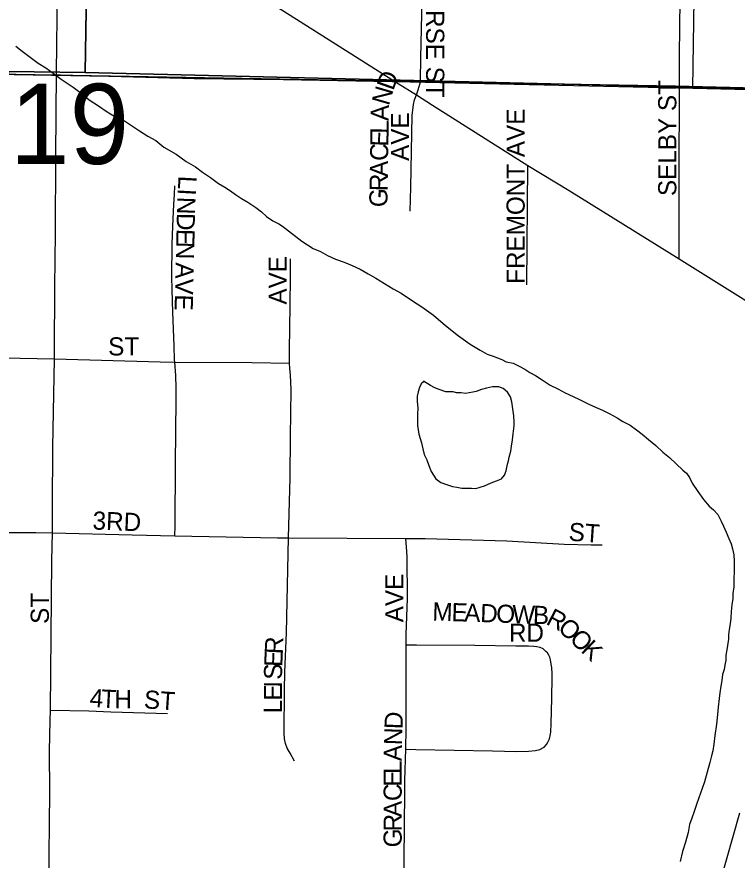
# Model space of a CAD drawing. Extents: x 0 to 68, y 0 to 52.9.
# Drawn here: x 44.4147 to 44.8116, y 37.5049 to 37.9697 of the extents above; entities that cross this region are included whole.
import ezdxf

# ---------------------------------------------------------------- set-up
doc = ezdxf.new("R2010")
doc.units = 0
for name, color, linetype in [('Default', 7, 'Continuous'), ('GM_X_Minor_Lake', 7, 'Continuous'), ('GM_X_Minor_River', 7, 'Continuous'), ('GM_X_State_Route', 7, 'Continuous'), ('GM_X_Township', 7, 'Continuous'), ('GM_X_Township_Road', 7, 'Continuous')]:
    doc.layers.add(name, color=color, linetype=linetype)

msp = doc.modelspace()

# ---------------------------------------------------------------- linework, layer by layer
at = {"layer": 'Default'}
for points in [[(43.1609, 39.26536), (44.47349, 39.25009), (44.45233, 37.93902), (44.41032, 37.93957), (43.13273, 37.95279)], [(45.79985, 39.21605), (45.7821, 37.90702), (45.7586, 37.9073), (44.45233, 37.93902), (44.47349, 39.25009)], [(44.41032, 37.93957), (44.45233, 37.93902), (45.7586, 37.9073), (45.68961, 36.62483), (44.34414, 36.66665)]]:
    msp.add_lwpolyline(points, close=True, dxfattribs=at)
for points in [[(44.63484, 37.92679), (44.63585, 37.92946), (44.63699, 37.93323), (44.63703, 37.93498), (44.63731, 37.94701), (44.63811, 37.97967), (44.63852, 37.99959), (44.63871, 38.02121), (44.63881, 38.07442), (44.63854, 38.0814)], [(44.43533, 37.78123), (44.43536, 37.78496), (44.43555, 37.82108), (44.43597, 37.85053), (44.43607, 37.89319), (44.43648, 37.93913), (44.43704, 37.9848), (44.4374, 38.00679), (44.43731, 38.02977), (44.43752, 38.05165)], [(44.77962, 37.83631), (44.77965, 37.84375), (44.77967, 37.84635), (44.77965, 37.87219), (44.77965, 37.88197), (44.77985, 37.93041), (44.77993, 37.94854), (44.78032, 37.97938), (44.78019, 37.98435), (44.78014, 37.99056)], [(44.63141, 37.86268), (44.63174, 37.87595), (44.63253, 37.9154), (44.63319, 37.92146), (44.63378, 37.924), (44.63484, 37.92679)], [(44.69572, 37.82197), (44.69622, 37.88784)], [(44.50166, 37.7794), (44.50157, 37.78074), (44.50129, 37.78834), (44.50061, 37.80689), (44.50017, 37.81925), (44.50005, 37.82665), (44.50028, 37.8444), (44.50061, 37.85432), (44.50125, 37.86631), (44.50156, 37.8718), (44.50177, 37.87669)], [(44.56492, 37.77879), (44.56494, 37.786), (44.56529, 37.81058), (44.56556, 37.82637), (44.56548, 37.83171), (44.56538, 37.83645)], [(44.28088, 37.78471), (44.30189, 37.78421), (44.34421, 37.7832), (44.38776, 37.78219), (44.43533, 37.78123)], [(44.43422, 37.68534), (44.43437, 37.69969), (44.43456, 37.73249), (44.43533, 37.78123)], [(44.43533, 37.78123), (44.49355, 37.77964), (44.50166, 37.7794)], [(44.50163, 37.68374), (44.50182, 37.68912), (44.50211, 37.72346), (44.50246, 37.75866), (44.5024, 37.76532), (44.50221, 37.77205), (44.50166, 37.7794)], [(44.50166, 37.7794), (44.5442, 37.77925), (44.56492, 37.77879)], [(44.56431, 37.6826), (44.56532, 37.71582), (44.56543, 37.73845), (44.56575, 37.76413), (44.56538, 37.77245), (44.56513, 37.77594), (44.56492, 37.77879)], [(44.38451, 37.68566), (44.39399, 37.68548), (44.4251, 37.68558), (44.43422, 37.68534)], [(44.43311, 37.58761), (44.43401, 37.67016), (44.43422, 37.68534)], [(44.43422, 37.68534), (44.47813, 37.68415), (44.50163, 37.68374)], [(44.50163, 37.68374), (44.55832, 37.68266), (44.56431, 37.6826)], [(44.56769, 37.55952), (44.56525, 37.56381), (44.56366, 37.56669), (44.56275, 37.56915), (44.56221, 37.57172), (44.56193, 37.57499), (44.56218, 37.5987), (44.56239, 37.60856), (44.5633, 37.63021), (44.56431, 37.6826)], [(44.56431, 37.6826), (44.62906, 37.68226)], [(44.62906, 37.68226), (44.63965, 37.68228), (44.68469, 37.68085), (44.71637, 37.67916), (44.73118, 37.6787), (44.73723, 37.67871)], [(44.62927, 37.62366), (44.62929, 37.62932), (44.62989, 37.64908), (44.62976, 37.67187), (44.62954, 37.6751), (44.62906, 37.68226)], [(44.62898, 37.56606), (44.62917, 37.57739), (44.62917, 37.58394), (44.62919, 37.59986), (44.62927, 37.62366)], [(44.62927, 37.62366), (44.63494, 37.62361), (44.66708, 37.62335), (44.68969, 37.62303), (44.69656, 37.62302), (44.69967, 37.62281), (44.70128, 37.62265), (44.70293, 37.62226), (44.70451, 37.6215), (44.70616, 37.61999)], [(44.70529, 37.56721), (44.7065, 37.56866), (44.70732, 37.56994), (44.70815, 37.57184), (44.70878, 37.57437), (44.70893, 37.57558), (44.70922, 37.58007), (44.70948, 37.59427), (44.70963, 37.60579), (44.70961, 37.60763), (44.70941, 37.6111), (44.70918, 37.61302), (44.70876, 37.6153), (44.70838, 37.61675), (44.70787, 37.61789), (44.70704, 37.6191), (44.70616, 37.61999)], [(44.43227, 37.4907), (44.43277, 37.54226), (44.43273, 37.56524), (44.43292, 37.58162), (44.43311, 37.58761)], [(44.43311, 37.58761), (44.45439, 37.58713), (44.46649, 37.58674), (44.49765, 37.58571)], [(44.62788, 37.48889), (44.62836, 37.52296), (44.62854, 37.54361), (44.62857, 37.54875), (44.62898, 37.56606)], [(44.62898, 37.56606), (44.6345, 37.56595), (44.67687, 37.56517), (44.6901, 37.56488), (44.69671, 37.56506), (44.70044, 37.56534), (44.70295, 37.56594), (44.70529, 37.56721)], [(44.7737, 37.38631), (44.77418, 37.38918), (44.77571, 37.39488), (44.79524, 37.46651), (44.8022, 37.49277), (44.81318, 37.53091)]]:
    msp.add_lwpolyline(points, dxfattribs=at)
at = {"layer": 'GM_X_Minor_Lake'}
for points in [[(44.64267, 37.76648), (44.63871, 37.76897), (44.6387, 37.76856), (44.63747, 37.76739), (44.63663, 37.7654), (44.63578, 37.76301), (44.63533, 37.76061), (44.63527, 37.7578), (44.6356, 37.75418), (44.63553, 37.75057), (44.6354, 37.74456), (44.63576, 37.74214), (44.63611, 37.73973), (44.63686, 37.73731), (44.63762, 37.73488), (44.63835, 37.73166), (44.63909, 37.72844), (44.64064, 37.7256), (44.64178, 37.72236), (44.64292, 37.71913), (44.64564, 37.71506), (44.64841, 37.713), (44.652, 37.71173), (44.65479, 37.71087), (44.65719, 37.71042), (44.65999, 37.70996), (44.6632, 37.70989), (44.6652, 37.70986), (44.66761, 37.70981), (44.67003, 37.71056), (44.67246, 37.71131), (44.6761, 37.71284), (44.67893, 37.71399), (44.68176, 37.71514), (44.68341, 37.71711), (44.68426, 37.7195), (44.68514, 37.72309), (44.68558, 37.72509), (44.68602, 37.72709), (44.68689, 37.73028), (44.68734, 37.73308), (44.68782, 37.73668), (44.68828, 37.73988), (44.68877, 37.74429), (44.68882, 37.74629), (44.68849, 37.74991), (44.68744, 37.75755), (44.68669, 37.76038), (44.68514, 37.76281), (44.68277, 37.76487), (44.68038, 37.76572), (44.67677, 37.76579), (44.67354, 37.76505), (44.67072, 37.76431), (44.66789, 37.76316), (44.66587, 37.7628), (44.66386, 37.76244), (44.66185, 37.76208), (44.65945, 37.76253), (44.65704, 37.76258), (44.65504, 37.76302), (44.65304, 37.76306), (44.65103, 37.7631)], [(44.65103, 37.7631), (44.64745, 37.76438), (44.64505, 37.76523), (44.64267, 37.76648)]]:
    msp.add_lwpolyline(points, dxfattribs=at)
at = {"layer": 'GM_X_Minor_River'}
for points in [[(44.4141, 37.95364), (44.41765, 37.95076), (44.422, 37.94746), (44.42635, 37.94416), (44.43071, 37.94167), (44.43466, 37.93878), (44.43901, 37.93548), (44.44574, 37.93093), (44.45009, 37.92763), (44.45443, 37.92394), (44.45958, 37.92062), (44.46393, 37.91773)], [(44.46393, 37.91773), (44.46869, 37.91482), (44.47347, 37.91272), (44.47782, 37.90982), (44.48218, 37.90693), (44.48693, 37.90402), (44.4913, 37.90153), (44.49564, 37.89783), (44.50239, 37.89408), (44.50792, 37.88996), (44.51308, 37.88705), (44.51703, 37.88416), (44.52139, 37.88126), (44.52574, 37.87797), (44.52931, 37.87589), (44.53248, 37.87382), (44.53524, 37.87176), (44.53841, 37.86969), (44.54198, 37.86761), (44.54634, 37.86471), (44.5495, 37.86224), (44.55226, 37.85978), (44.55582, 37.8573), (44.559, 37.85563), (44.56098, 37.85439), (44.57165, 37.84615), (44.57481, 37.84408), (44.57798, 37.84201), (44.58196, 37.84032), (44.58593, 37.83823), (44.59031, 37.83614), (44.59509, 37.83444), (44.59947, 37.83275), (44.60384, 37.83065), (44.6082, 37.82816), (44.61257, 37.82566), (44.61733, 37.82276), (44.62208, 37.81985), (44.62645, 37.81736), (44.63278, 37.81322), (44.63793, 37.8099), (44.64426, 37.80536), (44.65097, 37.79961), (44.65807, 37.79385), (44.66441, 37.78931), (44.66996, 37.78599), (44.67393, 37.7839), (44.67711, 37.78264), (44.6795, 37.78179), (44.68189, 37.78093), (44.68428, 37.77968), (44.68827, 37.7788), (44.69145, 37.77713), (44.69463, 37.77546), (44.6974, 37.7738), (44.70058, 37.77213), (44.70414, 37.76965), (44.7085, 37.76676), (44.71287, 37.76466), (44.71684, 37.76258), (44.72121, 37.76048), (44.72479, 37.75881), (44.72995, 37.75629), (44.73353, 37.75462), (44.73751, 37.75293), (44.74148, 37.75085), (44.74545, 37.74876), (44.74862, 37.74669), (44.75259, 37.7446), (44.75616, 37.74212), (44.75932, 37.73966), (44.76287, 37.73677), (44.76682, 37.73349), (44.77075, 37.72979), (44.77431, 37.72691), (44.78179, 37.71994), (44.78377, 37.7183), (44.78532, 37.71586), (44.78686, 37.71262), (44.78998, 37.70814), (44.7931, 37.70367), (44.79624, 37.69999), (44.7986, 37.69794), (44.80096, 37.69549), (44.80289, 37.69183), (44.80404, 37.689), (44.80558, 37.68576), (44.80711, 37.68212), (44.80826, 37.67929), (44.809, 37.67647), (44.80974, 37.67324), (44.81007, 37.66962), (44.80996, 37.66441), (44.80987, 37.6596), (44.80978, 37.65559), (44.80931, 37.65198), (44.80925, 37.64918), (44.80878, 37.64558), (44.8083, 37.64198), (44.80823, 37.63837), (44.80777, 37.63516)], [(44.80777, 37.63516), (44.8073, 37.63196), (44.80684, 37.62917), (44.80679, 37.62676), (44.80632, 37.62316), (44.80587, 37.62076), (44.80541, 37.61796), (44.80535, 37.61515), (44.80489, 37.61235), (44.80444, 37.60996), (44.80359, 37.60716), (44.80312, 37.60396), (44.80265, 37.60076), (44.80218, 37.59716), (44.80171, 37.59396), (44.80121, 37.58916), (44.80073, 37.58516), (44.80022, 37.57995), (44.79929, 37.57355), (44.79879, 37.56875), (44.79832, 37.56514), (44.79746, 37.56235), (44.79658, 37.55876), (44.79356, 37.54799), (44.79228, 37.5444), (44.79057, 37.53922), (44.78929, 37.53564), (44.78801, 37.53165), (44.78673, 37.52806), (44.78545, 37.52448), (44.78456, 37.52008), (44.78325, 37.51489), (44.78154, 37.50971), (44.78023, 37.50412)]]:
    msp.add_lwpolyline(points, dxfattribs=at)
at = {"layer": 'GM_X_State_Route'}
msp.add_lwpolyline([(44.54231, 37.98537), (44.58338, 37.95928), (44.62473, 37.93299), (44.63484, 37.92679), (44.64377, 37.92108), (44.69622, 37.88784), (44.71909, 37.87397), (44.77962, 37.83631), (44.81636, 37.81343), (44.83491, 37.80242), (44.86599, 37.78206), (44.88016, 37.77305), (44.9046, 37.75749), (44.95765, 37.72432), (44.9925, 37.70213), (45.02038, 37.68482), (45.05414, 37.66367), (45.06975, 37.6539), (45.09194, 37.63991), (45.14814, 37.60465), (45.20303, 37.57021), (45.21358, 37.56348)], dxfattribs=at)
at = {"layer": 'GM_X_Township'}
for points in [[(50.34506, 37.77433), (49.87003, 37.78728), (49.7424, 37.78907), (49.09193, 37.81286), (48.42924, 37.83782), (47.97584, 37.8521), (47.09341, 37.87493), (46.43542, 37.88698), (45.78152, 37.90751), (45.76356, 37.9078), (44.77759, 37.93161), (44.12143, 37.94309), (43.3203, 37.94792), (43.31455, 37.9477), (43.13228, 37.95106), (43.13722, 38.12535), (43.1394, 38.18651), (43.13947, 38.19396), (43.15039, 38.61621), (43.15805, 38.89613)], [(43.06441, 32.7683), (43.08393, 33.99592), (43.08445, 34.02868), (43.09249, 34.65268), (43.09292, 34.68642), (43.10458, 35.31419), (43.1053, 35.34562), (43.1113, 36.01383), (43.1191, 36.64269), (43.12347, 37.01757), (43.12518, 37.25841), (43.12908, 37.42523), (43.12464, 37.49311), (43.12504, 37.51468), (43.13199, 37.8314), (43.13205, 37.85841), (43.13228, 37.95106), (43.31455, 37.9477), (43.3203, 37.94792), (44.12143, 37.94309), (44.77759, 37.93161), (45.76356, 37.9078)]]:
    msp.add_lwpolyline(points, dxfattribs=at)
at = {"layer": 'GM_X_Township_Road'}
for points in [[(44.7872, 37.93047), (44.78916, 38.0655), (44.79016, 38.11876), (44.79071, 38.17209), (44.79244, 38.2459), (44.79316, 38.30333), (44.79602, 38.45915), (44.79696, 38.52068), (44.79793, 38.56987), (44.79919, 38.6847), (44.79993, 38.77083), (44.80072, 38.85276), (44.80196, 38.93851), (44.80314, 39.05312), (44.80377, 39.09415), (44.80406, 39.13866), (44.8054, 39.1908), (44.80605, 39.24618)], [(44.13006, 37.94547), (44.13366, 37.9422), (44.13919, 37.94017), (44.1456, 37.93958), (44.15418, 37.93958), (44.17426, 37.93982), (44.21509, 37.93939), (44.30327, 37.93917), (44.43863, 37.93782), (44.51244, 37.93583), (44.56165, 37.93528), (44.63137, 37.93387), (44.7872, 37.93047)], [(44.7872, 37.93047), (44.85691, 37.92882), (44.93892, 37.9272), (45.11526, 37.9236), (45.28748, 37.91961), (45.33668, 37.91828), (45.4638, 37.91529), (45.57041, 37.9127), (45.66883, 37.91037), (45.75084, 37.90855), (45.76151, 37.90822)]]:
    msp.add_lwpolyline(points, dxfattribs=at)

# ---------------------------------------------------------------- texts
at = {"layer": 'Default'}
for s, height, rotation, p in [('MORSE ST', 0.01, 270, (44.64022, 37.99506)), ('D', 0.01, 70.549, (44.62208, 37.9287)), ('19', 0.0442, 0, (44.41085, 37.88865)), ('N', 0.01, 73.6733, (44.61965, 37.92039)), ('SELBY ST', 0.01, 90, (44.77813, 37.87098)), ('A', 0.01, 89.0819, (44.61962, 37.91229)), ('AVE', 0.01, 90, (44.63078, 37.89034)), ('FREMONT AVE', 0.01, 90, (44.69453, 37.82258)), ('L', 0.01, 89.0711, (44.6195, 37.90525)), ('E', 0.01, 89.0711, (44.61939, 37.89821)), ('C', 0.01, 89.0771, (44.61926, 37.89029)), ('A', 0.01, 89.0819, (44.61912, 37.88149)), ('L', 0.01, 266.8838, (44.50381, 37.88231)), ('R', 0.01, 89.0771, (44.61899, 37.87357)), ('I', 0.01, 266.8517, (44.50343, 37.87528)), ('G', 0.01, 89.0819, (44.61885, 37.86478)), ('N', 0.01, 268.045, (44.50318, 37.87066)), ('D', 0.01, 268.8218, (44.50287, 37.86172)), ('E', 0.01, 268.5795, (44.50269, 37.85293)), ('N', 0.01, 268.5966, (44.50252, 37.84589)), ('AVE', 0.01, 90, (44.56341, 37.81114)), ('A', 0.01, 268.5853, (44.50224, 37.83445)), ('V', 0.01, 268.5966, (44.50202, 37.82565)), ('E', 0.01, 268.5795, (44.5018, 37.81685)), ('ST', 0.01, 0, (44.46498, 37.7831)), ('3RD', 0.01, 357.7987, (44.45625, 37.68718)), ('ST', 0.01, 356.1888, (44.71854, 37.68102)), ('AVE', 0.01, 90, (44.62765, 37.63602)), ('ST', 0.01, 90, (44.43229, 37.63514)), ('M', 0.01, 358.1236, (44.64353, 37.63702)), ('E', 0.01, 358.1599, (44.65409, 37.63667)), ('A', 0.01, 358.12, (44.66112, 37.63645)), ('D', 0.01, 358.1463, (44.66992, 37.63616)), ('O', 0.01, 358.12, (44.67872, 37.63588)), ('W', 0.01, 358.1408, (44.68752, 37.63559)), ('B', 0.01, 358.1297, (44.69895, 37.63521)), ('R', 0.01, 332.3489, (44.70573, 37.63526)), ('O', 0.01, 318.263, (44.71221, 37.63195)), ('RD', 0.01, 0, (44.68585, 37.62528)), ('O', 0.01, 316.1282, (44.7187, 37.62616)), ('R', 0.01, 87.4007, (44.5612, 37.61829)), ('K', 0.01, 316.1307, (44.72505, 37.62006)), ('E', 0.01, 87.622, (44.56091, 37.61127)), ('S', 0.01, 88.9618, (44.56079, 37.60429)), ('I', 0.01, 89.9573, (44.56078, 37.59994)), ('E', 0.01, 89.9453, (44.56078, 37.5929)), ('4', 0.01, 356.0323, (44.45455, 37.5895)), ('T', 0.01, 357.0939, (44.4609, 37.58906)), ('H', 0.01, 359.5719, (44.46841, 37.58869)), ('ST', 0.01, 356.1879, (44.48446, 37.58862)), ('L', 0.01, 89.9727, (44.56077, 37.58586)), ('D', 0.01, 87.726, (44.62719, 37.57694)), ('N', 0.01, 87.9452, (44.62688, 37.56816)), ('A', 0.01, 89.3879, (44.62678, 37.55943)), ('L', 0.01, 89.9727, (44.62678, 37.55241)), ('E', 0.01, 89.9821, (44.62678, 37.54538)), ('C', 0.01, 89.9757, (44.62678, 37.53746)), ('A', 0.01, 89.9928, (44.62678, 37.52866)), ('R', 0.01, 89.994, (44.62678, 37.52074)), ('G', 0.01, 89.9781, (44.62677, 37.51194))]:
    msp.add_text(s, height=height, rotation=rotation, dxfattribs=at).set_placement(p)

doc.saveas('drawing.dxf')
